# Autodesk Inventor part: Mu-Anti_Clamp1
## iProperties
Shininess: 64.0
Length Units: 11272
Angle Units: 11279
Time Units: 11290
Mass Units: 11286
Length Display Precision: 3
Angle Display Precision: 2
Compacted: True
Part Number: Mu-Anti_Clamp1
Document SubType Name: Modeling
Created: 2004-08
Designer: John Blackburn
Manufacturer: Standard
Standards Organization: Custom
Material: Aluminum-6061
Density: 0.0
Volumn: 0.0
Area: 0.0
PropertySet Name: Model Information
Control State: 0
Master: False
Checked Out: False
Author: John Blackburn
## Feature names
1. Extrusion1
2. Extrusion2
3. Hole1
